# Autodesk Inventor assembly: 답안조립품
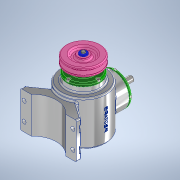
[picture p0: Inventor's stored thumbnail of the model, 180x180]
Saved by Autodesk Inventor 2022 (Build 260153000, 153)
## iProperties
Created: 2023-04
Part Number: 답안조립품
Document SubType Name: Assembly
Designer: Admin
Author: Admin
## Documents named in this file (17)
- C:\Users\Admin\Desktop\730411V1005\답안조립품.iam
- C:\Users\Admin\Desktop\730411V1005\본체.ipt
- C:\Users\Admin\Desktop\730411V1005\커버.ipt
- C:\Users\Admin\Desktop\730411V1005\베어링 6203.ipt
- C:\Users\Admin\Desktop\730411V1005\오일실 17 x 32 x 8.ipt
- C:\Users\Admin\Desktop\730411V1005\메인 축.ipt
- 메인 축.ipt
- C:\Users\Admin\Desktop\730411V1005\키 5 x 5 x 14.ipt
- C:\Users\Admin\Desktop\730411V1005\메인 베벨기어.ipt
- C:\Users\Admin\Desktop\730411V1005\서브 축.ipt
- 서브 축.ipt
- C:\Users\Admin\Desktop\730411V1005\서브 베벨기어.ipt
- C:\Users\Admin\Desktop\730411V1005\키 4 x 4 x 14.ipt
- C:\Users\Admin\Desktop\730411V1005\V-벨트풀리.ipt
- C:\Users\Admin\Desktop\730411V1005\볼트 M4 x 10.ipt
- C:\Users\Admin\Desktop\730411V1005\와셔 4 x 16.ipt
- C:\Users\Admin\Desktop\730411V1005\육각볼트 M4 x 8.ipt
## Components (1 placed, 1 different names)
1. V-벨트풀리:1
